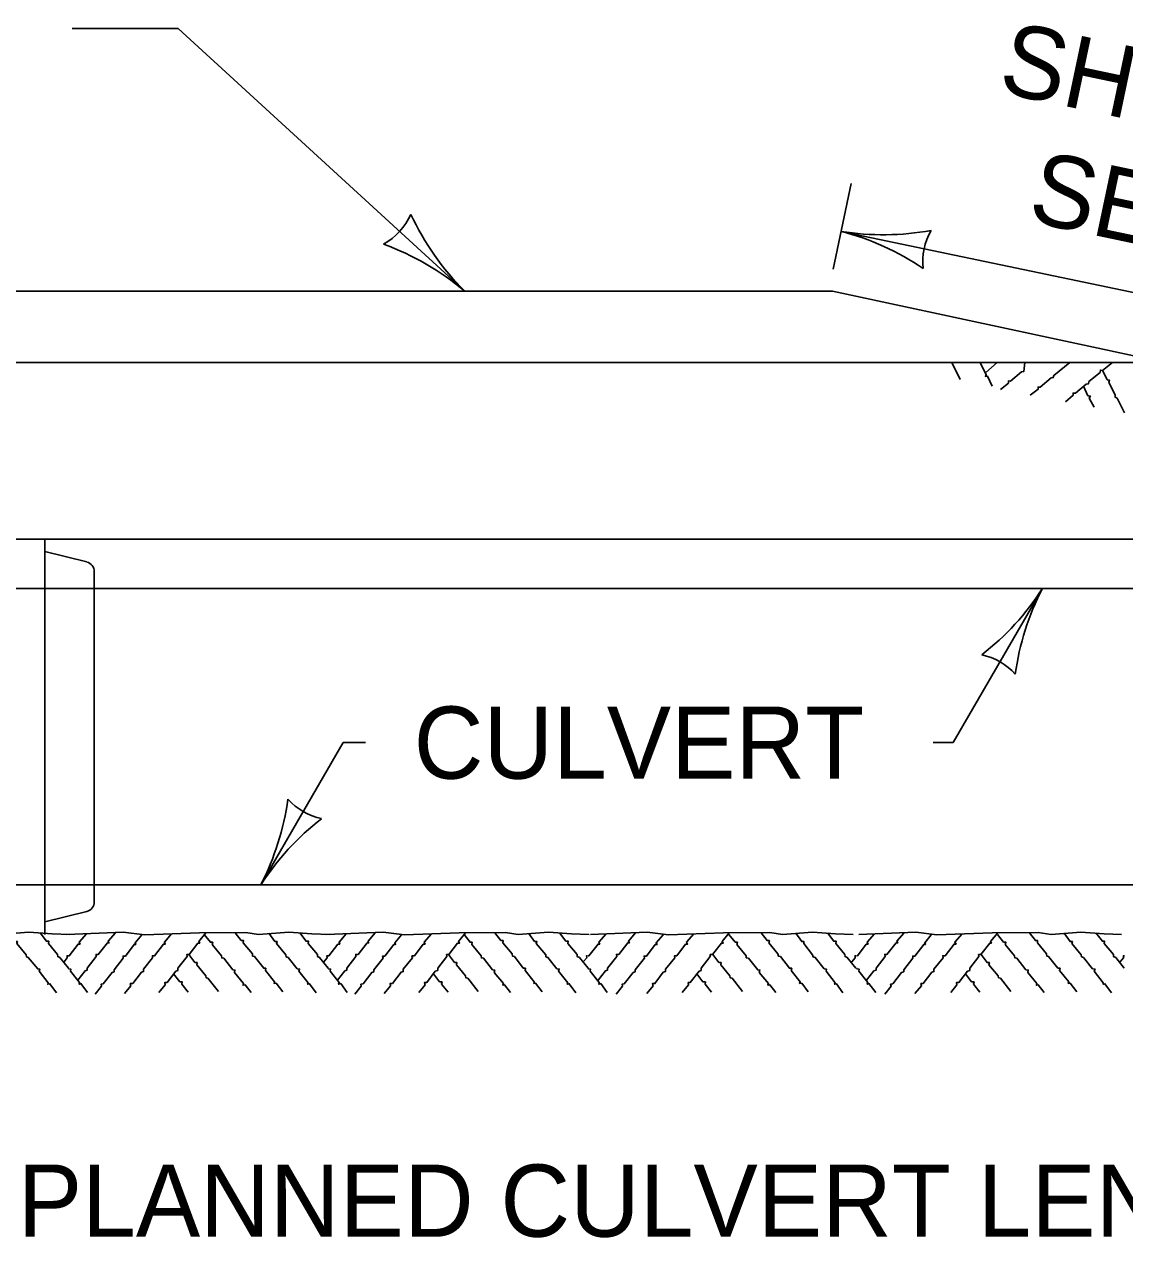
# Model space of a CAD drawing. Extents: x 49991.4 to 50022.1, y 49985 to 50011.4.
# Drawn here: x 50013.153 to 50014.068, y 49996.961 to 49997.97 of the extents above; entities that cross this region are included whole.
import ezdxf

# ---------------------------------------------------------------- set-up
doc = ezdxf.new("R2010")
doc.units = 0
for name, color, linetype in [('Level 1', 7, 'Continuous'), ('Level 2', 7, 'Continuous'), ('Level 3', 7, 'Continuous'), ('Level 4', 7, 'Continuous')]:
    doc.layers.add(name, color=color, linetype=linetype)

msp = doc.modelspace()

# ---------------------------------------------------------------- linework, layer by layer
at = {"layer": 'Level 1'}
for p, q in [((50012.6493, 49997.7486), (50013.8245, 49997.7486)), ((50013.8245, 49997.7486), (50014.1009, 49997.6892)), ((50014.1009, 49997.6892), (50012.6491, 49997.6892)), ((50012.6493, 49997.5423), (50014.7997, 49997.5423)), ((50013.1697, 49997.5423), (50013.1697, 49997.2136))]:
    msp.add_line(p, q, dxfattribs=at)
for points in [[(50013.9307, 49997.675), (50013.9239, 49997.6892)], [(50013.9574, 49997.6696), (50013.9535, 49997.6778), (50013.9517, 49997.6776), (50013.9524, 49997.679), (50013.9473, 49997.6892)], [(50013.9616, 49997.6892), (50013.952, 49997.681)], [(50013.9844, 49997.6892), (50013.9836, 49997.6816), (50013.9817, 49997.6814), (50013.9727, 49997.6736), (50013.9709, 49997.6739), (50013.9709, 49997.672), (50013.9643, 49997.6667)], [(50014.0219, 49997.6892), (50014.0086, 49997.6784), (50014.0081, 49997.6766), (50014.0064, 49997.6763), (50013.9973, 49997.6686), (50013.9956, 49997.6688), (50013.9956, 49997.667), (50013.989, 49997.6619)], [(50014.0574, 49997.6892), (50014.0492, 49997.6824), (50014.0474, 49997.6829), (50014.0471, 49997.681), (50014.0378, 49997.6733), (50014.0375, 49997.6715), (50014.0356, 49997.6712), (50014.0266, 49997.6636), (50014.0246, 49997.6637), (50014.0246, 49997.6619), (50014.0183, 49997.6566)], [(50014.0675, 49997.6472), (50014.0612, 49997.6596), (50014.0596, 49997.6604), (50014.0597, 49997.662), (50014.0543, 49997.6727), (50014.0549, 49997.6745), (50014.053, 49997.6748), (50014.0495, 49997.6823)], [(50014.0422, 49997.652), (50014.0381, 49997.6596), (50014.039, 49997.6613), (50014.037, 49997.6616), (50014.0333, 49997.6694)], [(50012.9719, 49997.2135), (50013.0189, 49997.2154), (50013.0367, 49997.2133), (50013.0825, 49997.2148), (50013.1209, 49997.2151), (50013.1313, 49997.2136), (50013.1564, 49997.2154), (50013.1757, 49997.2142), (50013.1905, 49997.2135)], [(50013.1792, 49997.1651), (50013.1738, 49997.1725), (50013.1721, 49997.1721), (50013.1725, 49997.1734), (50013.1649, 49997.183), (50013.1654, 49997.1847), (50013.1637, 49997.1849), (50013.1559, 49997.1945), (50013.1543, 49997.195), (50013.1541, 49997.1967), (50013.1463, 49997.2059), (50013.1468, 49997.2076), (50013.1449, 49997.2076), (50013.1399, 49997.2145)], [(50013.1893, 49997.1855), (50013.1821, 49997.1945), (50013.1804, 49997.1951), (50013.1803, 49997.1968), (50013.1727, 49997.2059), (50013.1729, 49997.2079), (50013.1709, 49997.2079), (50013.1657, 49997.2148)], [(50013.1879, 49997.2135), (50013.2349, 49997.2154), (50013.2527, 49997.2133), (50013.2983, 49997.2148), (50013.3367, 49997.2151), (50013.3473, 49997.2136), (50013.3724, 49997.2154), (50013.3917, 49997.2142), (50013.4063, 49997.2135)], [(50013.2043, 49997.2141), (50013.1983, 49997.207), (50013.1989, 49997.2055), (50013.1973, 49997.2055), (50013.1899, 49997.1959), (50013.1889, 49997.1959)], [(50013.2283, 49997.2149), (50013.2223, 49997.2079), (50013.2229, 49997.2065), (50013.2217, 49997.2065), (50013.2141, 49997.1969), (50013.2122, 49997.1969), (50013.2123, 49997.1953), (50013.2047, 49997.1855), (50013.2047, 49997.1839), (50013.2031, 49997.1833), (50013.1971, 49997.1755)], [(50013.2503, 49997.2133), (50013.2447, 49997.2065), (50013.2453, 49997.2052), (50013.2439, 49997.2052), (50013.2367, 49997.1956), (50013.2347, 49997.1956), (50013.2349, 49997.1939), (50013.2272, 49997.1842), (50013.2272, 49997.1825), (50013.2255, 49997.1818), (50013.2182, 49997.1725), (50013.2164, 49997.1722), (50013.2167, 49997.1705), (50013.2115, 49997.1639)], [(50013.2751, 49997.2141), (50013.2691, 49997.207), (50013.2698, 49997.2055), (50013.2683, 49997.2055), (50013.2609, 49997.1959), (50013.2591, 49997.1959), (50013.2593, 49997.1941), (50013.2517, 49997.1847), (50013.2517, 49997.1827), (50013.2499, 49997.1821), (50013.2427, 49997.1727), (50013.2407, 49997.1727), (50013.2411, 49997.1707), (50013.2359, 49997.1644)], [(50013.3035, 49997.2149), (50013.2977, 49997.2076), (50013.2985, 49997.2064), (50013.2969, 49997.2064), (50013.2897, 49997.1968), (50013.2877, 49997.1968), (50013.2879, 49997.1951), (50013.2803, 49997.1855), (50013.2803, 49997.1836), (50013.2787, 49997.1831), (50013.2713, 49997.1737), (50013.2693, 49997.1735), (50013.2698, 49997.1716), (50013.2645, 49997.1653)], [(50013.3411, 49997.1653), (50013.3363, 49997.1716), (50013.3345, 49997.1713), (50013.3349, 49997.1727), (50013.3274, 49997.1819), (50013.3277, 49997.1839), (50013.3261, 49997.1841), (50013.3184, 49997.1937), (50013.3167, 49997.1941), (50013.3165, 49997.1959), (50013.3088, 49997.2051), (50013.3093, 49997.207), (50013.3073, 49997.207), (50013.3022, 49997.2135)], [(50013.3675, 49997.1659), (50013.3619, 49997.1731), (50013.3603, 49997.1728), (50013.3605, 49997.1741), (50013.3531, 49997.1835), (50013.3533, 49997.1854), (50013.3517, 49997.1855), (50013.3441, 49997.1953), (50013.3424, 49997.1956), (50013.3423, 49997.1974), (50013.3345, 49997.2065), (50013.3349, 49997.2085), (50013.3329, 49997.2085), (50013.3279, 49997.2149)], [(50013.3952, 49997.1651), (50013.3898, 49997.1725), (50013.3881, 49997.1721), (50013.3885, 49997.1734), (50013.3809, 49997.183), (50013.3814, 49997.1847), (50013.3795, 49997.1849), (50013.3719, 49997.1945), (50013.3703, 49997.195), (50013.3699, 49997.1967), (50013.3623, 49997.2059), (50013.3628, 49997.2076), (50013.3609, 49997.2076), (50013.3559, 49997.2145)], [(50013.4053, 49997.1855), (50013.3981, 49997.1945), (50013.3964, 49997.1951), (50013.3963, 49997.1968), (50013.3887, 49997.2059), (50013.3889, 49997.2079), (50013.3869, 49997.2079), (50013.3817, 49997.2148)], [(50013.4039, 49997.2135), (50013.4509, 49997.2154), (50013.4687, 49997.2133), (50013.5143, 49997.2148), (50013.5527, 49997.2151), (50013.5633, 49997.2136), (50013.5884, 49997.2154), (50013.6077, 49997.2142), (50013.6223, 49997.2135)], [(50013.4203, 49997.2141), (50013.4143, 49997.207), (50013.4149, 49997.2055), (50013.4133, 49997.2055), (50013.4059, 49997.1959), (50013.4049, 49997.1959)], [(50013.4443, 49997.2149), (50013.4384, 49997.2079), (50013.4389, 49997.2065), (50013.4377, 49997.2065), (50013.4301, 49997.1969), (50013.4282, 49997.1969), (50013.4283, 49997.1953), (50013.4207, 49997.1855), (50013.4207, 49997.1839), (50013.4191, 49997.1833), (50013.4131, 49997.1755)], [(50013.4663, 49997.2133), (50013.4607, 49997.2065), (50013.4613, 49997.2052), (50013.4599, 49997.2052), (50013.4523, 49997.1956), (50013.4505, 49997.1956), (50013.4509, 49997.1939), (50013.4432, 49997.1842), (50013.4432, 49997.1825), (50013.4415, 49997.1818), (50013.4342, 49997.1725), (50013.4324, 49997.1722), (50013.4327, 49997.1705), (50013.4275, 49997.1639)], [(50013.4911, 49997.2141), (50013.4851, 49997.207), (50013.4858, 49997.2055), (50013.4843, 49997.2055), (50013.4769, 49997.1959), (50013.4749, 49997.1959), (50013.4753, 49997.1941), (50013.4677, 49997.1847), (50013.4677, 49997.1827), (50013.4659, 49997.1821), (50013.4587, 49997.1727), (50013.4567, 49997.1727), (50013.4571, 49997.1707), (50013.4519, 49997.1644)], [(50013.5195, 49997.2149), (50013.5137, 49997.2076), (50013.5145, 49997.2064), (50013.5129, 49997.2064), (50013.5055, 49997.1968), (50013.5037, 49997.1968), (50013.5038, 49997.1951), (50013.4963, 49997.1855), (50013.4963, 49997.1836), (50013.4943, 49997.1831), (50013.4873, 49997.1737), (50013.4853, 49997.1735), (50013.4858, 49997.1716), (50013.4805, 49997.1653)], [(50013.5569, 49997.1653), (50013.5519, 49997.1716), (50013.5505, 49997.1713), (50013.5509, 49997.1727), (50013.5434, 49997.1819), (50013.5437, 49997.1839), (50013.5419, 49997.1841), (50013.5344, 49997.1937), (50013.5327, 49997.1941), (50013.5325, 49997.1959), (50013.5248, 49997.2051), (50013.5249, 49997.207), (50013.5233, 49997.207), (50013.5182, 49997.2135)], [(50013.5833, 49997.1659), (50013.5777, 49997.1731), (50013.5763, 49997.1728), (50013.5765, 49997.1741), (50013.5691, 49997.1835), (50013.5693, 49997.1854), (50013.5675, 49997.1855), (50013.5601, 49997.1953), (50013.5584, 49997.1956), (50013.5583, 49997.1974), (50013.5505, 49997.2065), (50013.5507, 49997.2085), (50013.5489, 49997.2085), (50013.5437, 49997.2149)], [(50013.6112, 49997.1651), (50013.6057, 49997.1725), (50013.6041, 49997.1721), (50013.6045, 49997.1734), (50013.5969, 49997.183), (50013.5974, 49997.1847), (50013.5955, 49997.1849), (50013.5879, 49997.1945), (50013.5863, 49997.195), (50013.5861, 49997.1967), (50013.5783, 49997.2059), (50013.5788, 49997.2076), (50013.5769, 49997.2076), (50013.5719, 49997.2145)], [(50013.6213, 49997.1855), (50013.6141, 49997.1945), (50013.6124, 49997.1951), (50013.6123, 49997.1968), (50013.6045, 49997.2059), (50013.6049, 49997.2079), (50013.6029, 49997.2079), (50013.5977, 49997.2148)], [(50013.6364, 49997.2141), (50013.6304, 49997.207), (50013.6311, 49997.2055), (50013.6297, 49997.2055), (50013.6221, 49997.1959), (50013.6213, 49997.1959)], [(50013.6233, 49997.2135), (50013.6705, 49997.2154), (50013.6883, 49997.2133), (50013.7339, 49997.2148), (50013.7725, 49997.2151), (50013.7829, 49997.2136), (50013.8079, 49997.2154), (50013.8272, 49997.2142), (50013.8419, 49997.2135)], [(50013.6609, 49997.2149), (50013.6549, 49997.2079), (50013.6557, 49997.2065), (50013.6544, 49997.2065), (50013.6469, 49997.1969), (50013.6449, 49997.1969), (50013.6453, 49997.1953), (50013.6375, 49997.1855), (50013.6375, 49997.1839), (50013.6358, 49997.1833), (50013.6298, 49997.1755)], [(50013.6837, 49997.2133), (50013.6779, 49997.2065), (50013.6787, 49997.2052), (50013.6772, 49997.2052), (50013.6699, 49997.1956), (50013.6679, 49997.1956), (50013.6682, 49997.1939), (50013.6605, 49997.1842), (50013.6605, 49997.1825), (50013.6589, 49997.1818), (50013.6515, 49997.1725), (50013.6497, 49997.1722), (50013.6501, 49997.1705), (50013.6448, 49997.1639)], [(50013.7093, 49997.2141), (50013.7033, 49997.207), (50013.7041, 49997.2055), (50013.7025, 49997.2055), (50013.6951, 49997.1959), (50013.6933, 49997.1959), (50013.6934, 49997.1941), (50013.6857, 49997.1847), (50013.6857, 49997.1827), (50013.6839, 49997.1821), (50013.6769, 49997.1727), (50013.6749, 49997.1727), (50013.6754, 49997.1707), (50013.6701, 49997.1644)], [(50013.7387, 49997.2149), (50013.7329, 49997.2076), (50013.7337, 49997.2064), (50013.7323, 49997.2064), (50013.7247, 49997.1968), (50013.7228, 49997.1968), (50013.7229, 49997.1951), (50013.7153, 49997.1855), (50013.7153, 49997.1836), (50013.7138, 49997.1831), (50013.7063, 49997.1737), (50013.7047, 49997.1735), (50013.7049, 49997.1716), (50013.6997, 49997.1653)], [(50013.7774, 49997.1653), (50013.7725, 49997.1716), (50013.7709, 49997.1713), (50013.7713, 49997.1727), (50013.7637, 49997.1819), (50013.7642, 49997.1839), (50013.7624, 49997.1841), (50013.7547, 49997.1937), (50013.7529, 49997.1941), (50013.7528, 49997.1959), (50013.7451, 49997.2051), (50013.7455, 49997.207), (50013.7437, 49997.207), (50013.7385, 49997.2135)], [(50013.8045, 49997.1659), (50013.7991, 49997.1731), (50013.7973, 49997.1728), (50013.7978, 49997.1741), (50013.7903, 49997.1835), (50013.7907, 49997.1854), (50013.7888, 49997.1855), (50013.7813, 49997.1953), (50013.7797, 49997.1956), (50013.7792, 49997.1974), (50013.7717, 49997.2065), (50013.7721, 49997.2085), (50013.7702, 49997.2085), (50013.7653, 49997.2149)], [(50013.8333, 49997.1651), (50013.8279, 49997.1725), (50013.8263, 49997.1721), (50013.8267, 49997.1734), (50013.8193, 49997.183), (50013.8195, 49997.1847), (50013.8177, 49997.1849), (50013.8103, 49997.1945), (50013.8085, 49997.195), (50013.8081, 49997.1967), (50013.8007, 49997.2059), (50013.8009, 49997.2076), (50013.7991, 49997.2076), (50013.7941, 49997.2145)], [(50013.8439, 49997.1855), (50013.8369, 49997.1945), (50013.8351, 49997.1951), (50013.8349, 49997.1968), (50013.8273, 49997.2059), (50013.8277, 49997.2079), (50013.8257, 49997.2079), (50013.8205, 49997.2148)], [(50013.8595, 49997.2141), (50013.8535, 49997.207), (50013.8542, 49997.2055), (50013.8527, 49997.2055), (50013.8453, 49997.1959), (50013.8445, 49997.1959)], [(50013.8465, 49997.2135), (50013.8938, 49997.2154), (50013.9113, 49997.2133), (50013.9573, 49997.2148), (50013.9957, 49997.2151), (50014.0063, 49997.2136), (50014.0312, 49997.2154), (50014.0504, 49997.2142), (50014.0649, 49997.2135)], [(50013.8842, 49997.2149), (50013.8782, 49997.2079), (50013.8789, 49997.2065), (50013.8775, 49997.2065), (50013.8699, 49997.1969), (50013.8681, 49997.1969), (50013.8683, 49997.1953), (50013.8608, 49997.1855), (50013.8608, 49997.1839), (50013.8591, 49997.1833), (50013.8529, 49997.1755)], [(50013.9067, 49997.2133), (50013.9013, 49997.2065), (50013.9019, 49997.2052), (50013.9005, 49997.2052), (50013.8931, 49997.1956), (50013.8913, 49997.1956), (50013.8914, 49997.1939), (50013.8839, 49997.1842), (50013.8839, 49997.1825), (50013.8819, 49997.1818), (50013.8747, 49997.1725), (50013.8729, 49997.1722), (50013.8734, 49997.1705), (50013.8681, 49997.1639)], [(50013.9323, 49997.2141), (50013.9263, 49997.207), (50013.9273, 49997.2055), (50013.9257, 49997.2055), (50013.9184, 49997.1959), (50013.9163, 49997.1959), (50013.9167, 49997.1941), (50013.9089, 49997.1847), (50013.9089, 49997.1827), (50013.9073, 49997.1821), (50013.8999, 49997.1727), (50013.8981, 49997.1727), (50013.8985, 49997.1707), (50013.8932, 49997.1644)], [(50013.9621, 49997.2149), (50013.9561, 49997.2076), (50013.9568, 49997.2064), (50013.9553, 49997.2064), (50013.9479, 49997.1968), (50013.9461, 49997.1968), (50013.9463, 49997.1951), (50013.9387, 49997.1855), (50013.9387, 49997.1836), (50013.9369, 49997.1831), (50013.9297, 49997.1737), (50013.9277, 49997.1735), (50013.9281, 49997.1716), (50013.9229, 49997.1653)], [(50014.0005, 49997.1653), (50013.9957, 49997.1716), (50013.9941, 49997.1713), (50013.9945, 49997.1727), (50013.9869, 49997.1819), (50013.9874, 49997.1839), (50013.9855, 49997.1841), (50013.9779, 49997.1937), (50013.9763, 49997.1941), (50013.9759, 49997.1959), (50013.9683, 49997.2051), (50013.9688, 49997.207), (50013.9669, 49997.207), (50013.9619, 49997.2135)], [(50014.0279, 49997.1659), (50014.0222, 49997.1731), (50014.0207, 49997.1728), (50014.0211, 49997.1741), (50014.0133, 49997.1835), (50014.0139, 49997.1854), (50014.0121, 49997.1855), (50014.0043, 49997.1953), (50014.0027, 49997.1956), (50014.0025, 49997.1974), (50013.9951, 49997.2065), (50013.9952, 49997.2085), (50013.9934, 49997.2085), (50013.9883, 49997.2149)], [(50014.0567, 49997.1651), (50014.0511, 49997.1725), (50014.0497, 49997.1721), (50014.0498, 49997.1734), (50014.0423, 49997.183), (50014.0429, 49997.1847), (50014.0409, 49997.1849), (50014.0333, 49997.1945), (50014.0317, 49997.195), (50014.0313, 49997.1967), (50014.0237, 49997.2059), (50014.0241, 49997.2076), (50014.0222, 49997.2076), (50014.0173, 49997.2145)], [(50014.0672, 49997.1855), (50014.0601, 49997.1945), (50014.0583, 49997.1951), (50014.0582, 49997.1968), (50014.0505, 49997.2059), (50014.0509, 49997.2079), (50014.0491, 49997.2079), (50014.0437, 49997.2148)], [(50013.1893, 49997.1959), (50013.1882, 49997.1959), (50013.1883, 49997.1941), (50013.1857, 49997.1907)], [(50013.3141, 49997.1661), (50013.3053, 49997.1771), (50013.3037, 49997.1775), (50013.3035, 49997.1791), (50013.2959, 49997.1884), (50013.2962, 49997.1902), (50013.2944, 49997.1902), (50013.2893, 49997.1968)], [(50013.4049, 49997.1959), (50013.4042, 49997.1959), (50013.4043, 49997.1941), (50013.4017, 49997.1907)], [(50013.5301, 49997.1661), (50013.5213, 49997.1771), (50013.5197, 49997.1775), (50013.5194, 49997.1791), (50013.5119, 49997.1884), (50013.5121, 49997.1902), (50013.5104, 49997.1902), (50013.5053, 49997.1968)], [(50013.6209, 49997.1959), (50013.6201, 49997.1959), (50013.6203, 49997.1941), (50013.6173, 49997.1907)], [(50013.7498, 49997.1661), (50013.7413, 49997.1771), (50013.7395, 49997.1775), (50013.7391, 49997.1791), (50013.7317, 49997.1884), (50013.7319, 49997.1902), (50013.7301, 49997.1902), (50013.7251, 49997.1968)], [(50013.8441, 49997.1959), (50013.8434, 49997.1959), (50013.8435, 49997.1941), (50013.8407, 49997.1907)], [(50013.9729, 49997.1661), (50013.9643, 49997.1771), (50013.9627, 49997.1775), (50013.9623, 49997.1791), (50013.9547, 49997.1884), (50013.9551, 49997.1902), (50013.9532, 49997.1902), (50013.9483, 49997.1968)], [(50014.0673, 49997.1959), (50014.0665, 49997.1959), (50014.0667, 49997.1941), (50014.0639, 49997.1907)], [(50013.2051, 49997.1653), (50013.1997, 49997.1727), (50013.1983, 49997.1722), (50013.1984, 49997.1735), (50013.1909, 49997.183), (50013.1912, 49997.1848), (50013.1895, 49997.1849), (50013.1889, 49997.1855)], [(50013.2889, 49997.1656), (50013.2835, 49997.1722), (50013.2839, 49997.1741), (50013.2819, 49997.1741), (50013.2767, 49997.1809)], [(50013.4211, 49997.1653), (50013.4157, 49997.1727), (50013.4139, 49997.1722), (50013.4144, 49997.1735), (50013.4069, 49997.183), (50013.4072, 49997.1848), (50013.4055, 49997.1849), (50013.4049, 49997.1855)], [(50013.5049, 49997.1656), (50013.4995, 49997.1722), (50013.4999, 49997.1741), (50013.4979, 49997.1741), (50013.4927, 49997.1809)], [(50013.6373, 49997.1653), (50013.6319, 49997.1727), (50013.6304, 49997.1722), (50013.6305, 49997.1735), (50013.6231, 49997.183), (50013.6233, 49997.1848), (50013.6217, 49997.1849), (50013.6213, 49997.1855)], [(50013.7241, 49997.1656), (50013.7187, 49997.1722), (50013.7189, 49997.1741), (50013.7169, 49997.1741), (50013.7119, 49997.1809)], [(50013.8607, 49997.1653), (50013.8549, 49997.1727), (50013.8535, 49997.1722), (50013.8539, 49997.1735), (50013.8464, 49997.183), (50013.8467, 49997.1848), (50013.8449, 49997.1849), (50013.8445, 49997.1855)], [(50013.9472, 49997.1656), (50013.9418, 49997.1722), (50013.9423, 49997.1741), (50013.9403, 49997.1741), (50013.9351, 49997.1809)]]:
    msp.add_lwpolyline(points, dxfattribs=at)
at = {"layer": 'Level 3'}
for p, q in [((50013.1924, 49997.9669), (50013.2804, 49997.9669)), ((50013.2804, 49997.9669), (50013.5188, 49997.7486)), ((50013.8251, 49997.7667), (50013.8402, 49997.8381)), ((50013.8318, 49997.7982), (50014.8104, 49997.5931)), ((50013.925, 49997.3731), (50013.9991, 49997.5013)), ((50013.4176, 49997.3731), (50013.3492, 49997.2547)), ((50013.4176, 49997.3731), (50013.4364, 49997.3731)), ((50013.925, 49997.3731), (50013.9084, 49997.3731))]:
    msp.add_line(p, q, dxfattribs=at)
for centre, radius, start, end in [((50013.4242, 49997.8352), 0.0548, 299.6524, 335.3747), ((50013.6755, 49997.9062), 0.2223, 204.9696, 225.1531), ((50013.8669, 49998.0191), 0.2237, 260.9697, 280.2195), ((50013.7793, 49997.5913), 0.2134, 55.5984, 75.7819), ((50013.9522, 49997.7729), 0.0526, 150.2812, 186.0035), ((50013.3701, 49997.5692), 0.233, 50.3409, 69.5907), ((50013.8189, 49997.6156), 0.2134, 307.4434, 327.6269), ((50014.1981, 49997.3991), 0.2237, 152.8147, 172.0645), ((50013.9376, 49997.3947), 0.0526, 42.1262, 77.8485), ((50013.1502, 49997.3569), 0.2237, 332.8229, 352.0727), ((50013.4108, 49997.3613), 0.0526, 222.1344, 257.8568), ((50013.5295, 49997.1404), 0.2134, 127.4516, 147.6351)]:
    msp.add_arc(centre, radius, start, end, dxfattribs=at)
at = {"layer": 'Level 4'}
for p, q in [((50013.1697, 49997.5321), (50013.2045, 49997.5233)), ((50013.2107, 49997.5152), (50013.2107, 49997.2408)), ((50012.6493, 49997.5013), (50014.8057, 49997.5013)), ((50012.6493, 49997.2547), (50015.1696, 49997.2547)), ((50013.1697, 49997.224), (50013.2046, 49997.2327))]:
    msp.add_line(p, q, dxfattribs=at)
for centre, start, end in [((50013.2025, 49997.5153), 0, 75.8893), ((50013.2025, 49997.2407), 284.1107, 0)]:
    msp.add_arc(centre, 0.00822, start, end, dxfattribs=at)

# ---------------------------------------------------------------- texts
at = {"layer": 'Level 2'}
for s, p in [('SHOULDER SLOPE', (50013.9609, 49997.9144)), ('SEE TYP. SECT.', (50013.9855, 49997.807))]:
    msp.add_text(s, height=0.06, rotation=348.1237, dxfattribs=at).set_placement(p)
for s, p in [('CULVERT', (50013.4764, 49997.3431)), ('PLANNED CULVERT LENGTH', (50013.1472, 49996.9622))]:
    msp.add_text(s, height=0.06, dxfattribs=at).set_placement(p)

doc.saveas('drawing.dxf')
